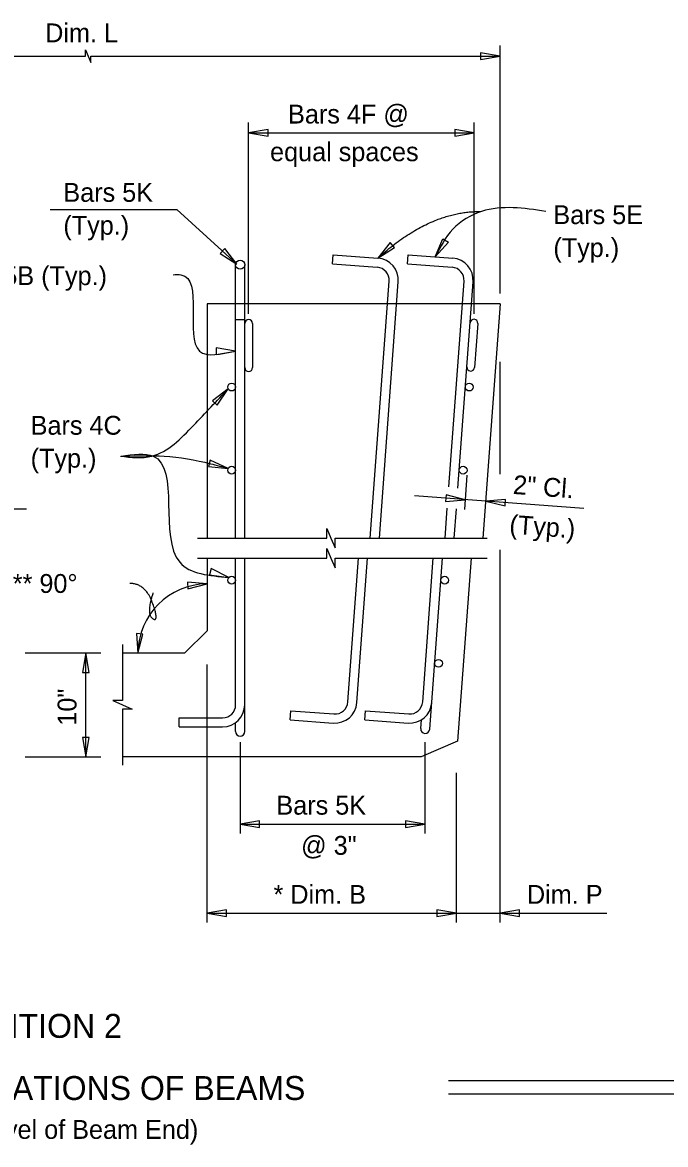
# Model space of a CAD drawing. Extents: x 120790.7 to 120844.8, y 120612.1 to 120653.6.
# Drawn here: x 120805.76 to 120810.92, y 120612.08 to 120621.08 of the extents above; entities that cross this region are included whole.
import ezdxf

# ---------------------------------------------------------------- set-up
doc = ezdxf.new("R2010")
doc.units = 0
for name, color, linetype in [('AdhocPoint_dp', 7, 'Continuous'), ('Patterning', 7, 'Continuous'), ('PlotBorder_dp', 7, 'Continuous'), ('SheetBorder_dp', 7, 'Continuous')]:
    doc.layers.add(name, color=color, linetype=linetype)

# ---------------------------------------------------------------- blocks, each defined once
blk = doc.blocks.new('Terminator-Arrow')
at = {"layer": 'PlotBorder_dp'}
blk.add_lwpolyline([(0, 0), (-0.00041, 0.000069), (-0.00041, -0.000069)], close=True, dxfattribs=at)

msp = doc.modelspace()

# ---------------------------------------------------------------- linework, layer by layer
at = {"layer": 'AdhocPoint_dp'}
for p, q in [((120809.5938, 120618.8231), (120807.243, 120618.8231)), ((120807.243, 120618.8231), (120807.243, 120616.945)), ((120809.5937, 120618.8231), (120809.455, 120616.945)), ((120807.243, 120616.7833), (120807.243, 120616.2011)), ((120809.3605, 120616.7833), (120809.2522, 120615.3161)), ((120807.0662, 120616.0244), (120807.243, 120616.2011)), ((120806.5656, 120616.0244), (120807.0662, 120616.0244)), ((120809.2522, 120615.3161), (120808.9605, 120615.1911)), ((120808.9605, 120615.1911), (120806.5656, 120615.1911))]:
    msp.add_line(p, q, dxfattribs=at)
at = {"layer": 'PlotBorder_dp'}
for p, q in [((120809.5937, 120618.9058), (120809.5937, 120620.8956)), ((120809.5937, 120618.9058), (120809.5937, 120620.8956)), ((120807.5763, 120618.7443), (120807.5763, 120620.2796)), ((120807.5763, 120618.7443), (120807.5763, 120620.2796)), ((120809.3862, 120618.7443), (120809.3862, 120620.2796)), ((120809.3862, 120618.7443), (120809.3862, 120620.2796)), ((120807.5761, 120620.1951), (120809.3861, 120620.1951)), ((120807.5761, 120620.1951), (120809.3861, 120620.1951)), ((120805.985, 120619.5819), (120806.9996, 120619.5819)), ((120805.985, 120619.5819), (120806.9996, 120619.5819)), ((120807.5086, 120619.1738), (120807.5086, 120619.1738)), ((120807.5086, 120619.1738), (120807.5086, 120619.1738)), ((120809.5937, 120617.4574), (120809.5937, 120618.3597)), ((120809.5937, 120617.4574), (120809.5937, 120618.3597)), ((120809.3279, 120617.4487), (120809.3077, 120617.1751)), ((120809.3279, 120617.4487), (120809.3077, 120617.1751)), ((120810.2645, 120617.1831), (120808.908, 120617.2832)), ((120810.2645, 120617.1831), (120808.908, 120617.2832)), ((120805.7938, 120617.1779), (120804.5091, 120617.1779)), ((120805.7938, 120617.1779), (120804.5091, 120617.1779)), ((120809.5937, 120613.8613), (120809.5937, 120616.8506)), ((120809.5937, 120613.8613), (120809.5937, 120616.8506)), ((120805.7843, 120616.0244), (120806.3924, 120616.0244)), ((120805.7843, 120616.0244), (120806.3924, 120616.0244)), ((120806.2716, 120615.1911), (120806.2716, 120616.0244)), ((120806.2716, 120615.1911), (120806.2716, 120616.0244)), ((120807.243, 120613.8613), (120807.243, 120615.9327)), ((120807.243, 120613.8613), (120807.243, 120615.9327)), ((120807.5086, 120615.3084), (120807.5086, 120614.5765)), ((120807.5086, 120615.3084), (120807.5086, 120614.5765)), ((120808.9905, 120615.3084), (120808.9905, 120614.5765)), ((120808.9905, 120615.3084), (120808.9905, 120614.5765)), ((120805.7843, 120615.1911), (120806.3924, 120615.1911)), ((120805.7843, 120615.1911), (120806.3924, 120615.1911)), ((120809.243, 120613.8613), (120809.243, 120615.0632)), ((120809.243, 120613.8613), (120809.243, 120615.0632)), ((120807.5086, 120614.6522), (120808.9905, 120614.6522)), ((120807.5086, 120614.6522), (120808.9905, 120614.6522)), ((120807.243, 120613.9369), (120810.4486, 120613.9369)), ((120807.243, 120613.9369), (120810.4486, 120613.9369)), ((120817.2776, 120612.5928), (120809.1791, 120612.5928)), ((120817.2776, 120612.5928), (120809.1791, 120612.5928)), ((120817.2776, 120612.4847), (120809.1791, 120612.4847)), ((120817.2776, 120612.4847), (120809.1791, 120612.4847))]:
    msp.add_line(p, q, dxfattribs=at)
for points in [[(120802.9857, 120620.8104), (120806.2671, 120620.8104), (120806.2671, 120620.8621), (120806.2896, 120620.8104), (120806.3121, 120620.7588), (120806.3121, 120620.8104), (120809.5936, 120620.8104)], [(120802.9857, 120620.8104), (120806.2671, 120620.8104), (120806.2671, 120620.8621), (120806.2896, 120620.8104), (120806.3121, 120620.7588), (120806.3121, 120620.8104), (120809.5936, 120620.8104)], [(120806.9996, 120619.5819), (120807.4825, 120619.1419)], [(120806.9996, 120619.5819), (120807.4825, 120619.1419)], [(120807.1673, 120616.9451), (120808.2027, 120616.9451), (120808.2027, 120617.0226), (120808.2364, 120616.9451), (120808.2702, 120616.8676), (120808.2702, 120616.9451), (120809.4885, 120616.9451)], [(120807.1673, 120616.9451), (120808.2027, 120616.9451), (120808.2027, 120617.0226), (120808.2364, 120616.9451), (120808.2702, 120616.8676), (120808.2702, 120616.9451), (120809.4885, 120616.9451)], [(120807.1673, 120616.7834), (120808.2027, 120616.7834), (120808.2027, 120616.8609), (120808.2364, 120616.7834), (120808.2702, 120616.7059), (120808.2702, 120616.7834), (120809.4885, 120616.7834)], [(120807.1673, 120616.7834), (120808.2027, 120616.7834), (120808.2027, 120616.8609), (120808.2364, 120616.7834), (120808.2702, 120616.7059), (120808.2702, 120616.7834), (120809.4885, 120616.7834)], [(120806.5656, 120616.0915), (120806.5656, 120615.6415), (120806.4881, 120615.6415), (120806.6431, 120615.574), (120806.5656, 120615.574), (120806.5656, 120615.124)], [(120806.5656, 120616.0915), (120806.5656, 120615.6415), (120806.4881, 120615.6415), (120806.6431, 120615.574), (120806.5656, 120615.574), (120806.5656, 120615.124)]]:
    msp.add_lwpolyline(points, dxfattribs=at)
for points in [[(120808.6133, 120619.1899), (120808.7465, 120619.2757), (120808.7108, 120619.3148)], [(120808.6133, 120619.1899), (120808.7465, 120619.2757), (120808.7108, 120619.3148)], [(120809.0723, 120619.2005), (120809.1344, 120619.3463), (120809.1789, 120619.3177)], [(120809.0723, 120619.2005), (120809.1344, 120619.3463), (120809.1789, 120619.3177)], [(120807.4825, 120619.1419), (120807.3849, 120619.2667), (120807.3492, 120619.2275)], [(120807.4825, 120619.1419), (120807.3849, 120619.2667), (120807.3492, 120619.2275)], [(120807.4721, 120618.4452), (120807.3159, 120618.4716), (120807.3159, 120618.4187)], [(120807.4721, 120618.4452), (120807.3159, 120618.4716), (120807.3159, 120618.4187)], [(120807.4131, 120618.1422), (120807.2862, 120618.0473), (120807.3246, 120618.0108)], [(120807.4131, 120618.1422), (120807.2862, 120618.0473), (120807.3246, 120618.0108)], [(120807.4127, 120617.5032), (120807.269, 120617.5699), (120807.255, 120617.5189)], [(120807.4127, 120617.5032), (120807.269, 120617.5699), (120807.255, 120617.5189)], [(120809.3135, 120617.2533), (120809.1597, 120617.2912), (120809.1558, 120617.2384)], [(120809.3135, 120617.2533), (120809.1597, 120617.2912), (120809.1558, 120617.2384)], [(120809.4798, 120617.2411), (120809.6337, 120617.2032), (120809.6376, 120617.2559)], [(120809.4798, 120617.2411), (120809.6337, 120617.2032), (120809.6376, 120617.2559)], [(120807.4188, 120616.6299), (120807.2773, 120616.701), (120807.2617, 120616.6504)], [(120807.4188, 120616.6299), (120807.2773, 120616.701), (120807.2617, 120616.6504)], [(120807.243, 120616.5778), (120807.0851, 120616.5909), (120807.0896, 120616.5382)], [(120807.243, 120616.5778), (120807.0851, 120616.5909), (120807.0896, 120616.5382)], [(120806.6882, 120616.0225), (120806.7293, 120616.1755), (120806.6767, 120616.1805)], [(120806.6882, 120616.0225), (120806.7293, 120616.1755), (120806.6767, 120616.1805)], [(120806.2716, 120616.0244), (120806.2452, 120615.8682), (120806.2981, 120615.8682)], [(120806.2716, 120616.0244), (120806.2452, 120615.8682), (120806.2981, 120615.8682)], [(120806.2716, 120615.1911), (120806.2981, 120615.3473), (120806.2452, 120615.3473)], [(120806.2716, 120615.1911), (120806.2981, 120615.3473), (120806.2452, 120615.3473)]]:
    msp.add_lwpolyline(points, close=True, dxfattribs=at)
msp.add_arc((120807.2473, 120616.0186), 0.5592, 90.45004, 179.60086, dxfattribs=at)
msp.add_arc((120807.2473, 120616.0186), 0.5592, 90.45004, 179.60086, dxfattribs=at)
for points in [[(120809.9593, 120619.5652), (120809.4449, 120619.5652), (120809.2148, 120619.4226), (120809.0724, 120619.2005)], [(120809.9593, 120619.5652), (120809.4449, 120619.5652), (120809.2148, 120619.4226), (120809.0724, 120619.2005)], [(120806.9722, 120619.0571), (120807.0328, 120619.0571), (120807.1825, 120618.4452), (120807.4721, 120618.4452)], [(120806.9722, 120619.0571), (120807.0328, 120619.0571), (120807.1825, 120618.4452), (120807.4721, 120618.4452)], [(120806.5478, 120617.6022), (120806.7999, 120617.6022), (120807.1341, 120617.8489), (120807.4131, 120618.1421)], [(120806.5478, 120617.6022), (120806.7999, 120617.6022), (120807.1341, 120617.8489), (120807.4131, 120618.1421)], [(120806.5533, 120617.6022), (120806.8122, 120617.6022), (120807.0239, 120616.7511), (120807.4188, 120616.6298)], [(120806.5533, 120617.6022), (120806.8122, 120617.6022), (120807.0239, 120616.7511), (120807.4188, 120616.6298)], [(120806.5807, 120617.6022), (120806.8985, 120617.6022), (120807.271, 120617.5419), (120807.4127, 120617.5032)], [(120806.5807, 120617.6022), (120806.8985, 120617.6022), (120807.271, 120617.5419), (120807.4127, 120617.5032)]]:
    msp.add_spline(points, degree=3, dxfattribs=at)
for points in [[(120808.6135, 120619.1901), (120809.0236, 120619.5648), (120809.4338, 120619.5648)], [(120808.6135, 120619.1901), (120809.0236, 120619.5648), (120809.4338, 120619.5648)], [(120806.8096, 120616.5051), (120806.7523, 120616.3332), (120806.8631, 120616.2645), (120806.7504, 120616.5815), (120806.6244, 120616.5815)], [(120806.8096, 120616.5051), (120806.7523, 120616.3332), (120806.8631, 120616.2645), (120806.7504, 120616.5815), (120806.6244, 120616.5815)]]:
    msp.add_open_spline(points, degree=2, dxfattribs=at)
at = {"layer": 'SheetBorder_dp'}
for p, q in [((120808.2499, 120619.1438), (120808.2553, 120619.2165)), ((120808.2553, 120619.2165), (120808.6135, 120619.1901)), ((120808.8499, 120619.1438), (120808.8553, 120619.2165)), ((120808.8553, 120619.2165), (120809.2135, 120619.1901)), ((120807.4721, 120616.945), (120807.4721, 120619.1363)), ((120807.545, 120616.945), (120807.545, 120619.1363)), ((120808.2499, 120619.1438), (120808.6081, 120619.1173)), ((120808.8499, 120619.1438), (120809.2081, 120619.1173)), ((120808.5522, 120616.945), (120808.7043, 120619.0058)), ((120808.6253, 120616.945), (120808.7771, 120619.0004)), ((120809.1825, 120617.3553), (120809.3043, 120619.0058)), ((120809.2549, 120617.3468), (120809.3771, 120619.0004)), ((120807.4721, 120618.6981), (120807.545, 120618.6981)), ((120807.6075, 120618.6668), (120807.6075, 120618.3127)), ((120809.4151, 120618.6668), (120809.389, 120618.3136)), ((120809.1522, 120616.945), (120809.1699, 120617.1847)), ((120809.2253, 120616.945), (120809.2426, 120617.1798)), ((120807.4721, 120615.6078), (120807.4721, 120616.7833)), ((120807.545, 120615.3942), (120807.545, 120616.7833)), ((120808.3726, 120615.6309), (120808.4577, 120616.7833)), ((120808.4453, 120615.6255), (120808.5308, 120616.7833)), ((120808.9726, 120615.6309), (120809.0577, 120616.7833)), ((120809.0296, 120615.4125), (120809.1308, 120616.7833)), ((120807.9087, 120615.4875), (120807.914, 120615.5603)), ((120807.914, 120615.5603), (120808.261, 120615.5346)), ((120808.5087, 120615.4875), (120808.514, 120615.5603)), ((120808.514, 120615.5603), (120808.861, 120615.5346)), ((120807.02, 120615.5036), (120807.3679, 120615.5036)), ((120807.02, 120615.4306), (120807.02, 120615.5036)), ((120807.4721, 120615.3942), (120807.4721, 120615.4645)), ((120807.9087, 120615.4875), (120808.2556, 120615.4619)), ((120808.5087, 120615.4875), (120808.8556, 120615.4619)), ((120808.9568, 120615.4179), (120808.962, 120615.488)), ((120807.02, 120615.4306), (120807.3679, 120615.4306))]:
    msp.add_line(p, q, dxfattribs=at)
for centre, radius in [((120807.5086, 120619.1373), 0.0365), ((120807.4409, 120618.1564), 0.0312), ((120809.346, 120618.1564), 0.0312), ((120807.4409, 120617.4898), 0.0312), ((120809.2968, 120617.4898), 0.0312), ((120807.4409, 120616.6077), 0.0312), ((120809.1491, 120616.6077), 0.0312), ((120809.0998, 120615.9411), 0.0312)]:
    msp.add_circle(centre, radius, dxfattribs=at)
for centre, radius, start, end in [((120808.6004, 120619.0134), 0.1771, 355.77659, 85.77659), ((120809.2004, 120619.0134), 0.1771, 355.77659, 85.77659), ((120808.6004, 120619.0134), 0.1042, 355.77659, 85.77659), ((120809.2004, 120619.0134), 0.1042, 355.77659, 85.77659), ((120807.5763, 120618.6668), 0.0312, 0, 180), ((120809.3839, 120618.6691), 0.0312, 355.77659, 175.77659), ((120809.3579, 120618.3159), 0.0312, 175.77659, 355.77659), ((120807.5763, 120618.3127), 0.0312, 180, 0), ((120808.2686, 120615.6386), 0.1771, 265.77659, 355.77659), ((120808.2686, 120615.6386), 0.1042, 265.77659, 355.77659), ((120808.8686, 120615.6386), 0.1771, 265.77659, 355.77659), ((120808.8686, 120615.6386), 0.1042, 265.77659, 355.77659), ((120807.3679, 120615.6078), 0.1042, 270, 360), ((120807.3679, 120615.6078), 0.1771, 270, 360), ((120807.5086, 120615.3942), 0.0365, 180, 0), ((120808.9932, 120615.4152), 0.0365, 175.77659, 355.77659)]:
    msp.add_arc(centre, radius, start, end, dxfattribs=at)

# ---------------------------------------------------------------- block references
at = {"layer": 'PlotBorder_dp', "xscale": 381, "yscale": 384.0238095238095}
for p in [(120809.5935, 120620.81), (120809.5935, 120620.81), (120809.3859, 120620.1947), (120809.3859, 120620.1947), (120808.9903, 120614.6518), (120808.9903, 120614.6518), (120809.2429, 120613.9365), (120809.2429, 120613.9365)]:
    msp.add_blockref('Terminator-Arrow', p, dxfattribs=at)
at = {"layer": 'PlotBorder_dp', "xscale": 381, "yscale": 384.0238095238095, "rotation": 180}
for p in [(120807.576, 120620.1947), (120807.576, 120620.1947), (120807.5084, 120614.6518), (120807.5084, 120614.6518), (120807.2428, 120613.9366), (120807.2428, 120613.9366), (120809.5936, 120613.9366), (120809.5936, 120613.9366)]:
    msp.add_blockref('Terminator-Arrow', p, dxfattribs=at)

# ---------------------------------------------------------------- texts
at = {"layer": 'Patterning'}
for s, height, p in [('Dim. L', 0.1512, (120805.9449, 120620.9216)), ('Bars 4F @', 0.1512, (120807.8929, 120620.2703)), ('equal spaces', 0.1512, (120807.7485, 120619.9682)), ('Bars 5B (Typ.)', 0.1512, (120805.1374, 120618.9742)), ('** 90°', 0.1512, (120805.6851, 120616.5056)), ('Bars 5K', 0.1512, (120807.7993, 120614.7274)), ('@ 3"', 0.1512, (120807.9972, 120614.4053)), ('* Dim. B', 0.1512, (120807.7762, 120614.0122)), ('Dim. P', 0.1512, (120809.8087, 120614.0122)), ('CONDITION 2', 0.192, (120804.9048, 120612.9373)), ('SCHEMATIC END ELEVATIONS OF BEAMS', 0.192, (120802.8243, 120612.439)), ('(Showing Vertical Bevel of Beam End)', 0.1512, (120803.7453, 120612.1271))]:
    msp.add_text(s, height=height, dxfattribs=at).set_placement(p)
for s, rotation, p in [('2" Cl.', 355.77659, (120809.6931, 120617.2999)), ('(Typ.)', 355.77659, (120809.6642, 120616.9817)), ('10"', 90, (120806.1959, 120615.4409))]:
    msp.add_text(s, height=0.1512, rotation=rotation, dxfattribs=at).set_placement(p)
at = {"layer": 'PlotBorder_dp'}
for s, p in [('Bars 5K', (120806.0907, 120619.6423)), ('Bars 5E', (120810.0207, 120619.4635)), ('(Typ.)', (120806.0907, 120619.3783)), ('(Typ.)', (120810.0207, 120619.1995)), ('Bars 4C', (120805.8283, 120617.7743)), ('(Typ.)', (120805.8283, 120617.5103))]:
    msp.add_text(s, height=0.1512, dxfattribs=at).set_placement(p)

doc.saveas('drawing.dxf')
